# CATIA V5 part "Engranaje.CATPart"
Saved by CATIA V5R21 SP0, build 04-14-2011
Part number: Engranaje
Bounding box of the stored display mesh (mm): x -180 to 0, y -257.469 to 257.464, z -257.469 to 257.468
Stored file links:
  C:\Users\Juan y Virginia\Documents\Cauly\Apuntes\CAD\Catia\Cursos\Engranaje\Engranaje.CATPart
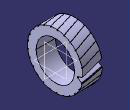
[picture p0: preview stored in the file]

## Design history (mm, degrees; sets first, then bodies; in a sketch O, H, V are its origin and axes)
Parameters
  `Modulo (m)` = 18 mm
  `Numero dientes (z)` = 25
  `Angulo de presion (alfa)` = 25 deg
  `Angulo de helice (beta)` = 15 deg
  `Tipo helice` = 1
  `Diametro eje (dj)` = 100 mm
  `Diametro primitivo (d)` = 465.8743 mm {= `Modulo (m)` *`Numero dientes (z)` /cos(`Angulo de helice (beta)` )}
  `Diametro base (db)` = 422.2255 mm {= `Diametro primitivo (d)` *cos(`Angulo de presion (alfa)` )}
  `Diametro exterior (de)` = 501.8743 mm {= `Diametro primitivo (d)` +2*`Modulo (m)`}
  `Diametro de fondo (df)` = 420.8743 mm {= `Diametro primitivo (d)` -2*`Dedendum (b)`}
  `Paso nominal (pn)` = 56.5487 mm {= PI * `Modulo (m)`}
  `Paso aparente (pa)` = 58.5435 mm {= `Paso nominal (pn)` / cos(`Angulo de helice (beta)` )}
  `Addendum (a)` = 18 mm {= `Modulo (m)`}
  `Dedendum (b)` = 22.5 mm {= 1.25 * `Modulo (m)`}
  `Espacio libre de fondo (c)` = 4.5 mm {= 0.25 * `Modulo (m)`}
  `Profundidad diente (h)` = 40.5 mm {= `Addendum (a)` +`Dedendum (b)`}
  `Radio de pie (r)` = 2.988 mm {= .166 * `Modulo (m)`}
  `Ancho de diente (B)` = 180 mm
  `Diametro de cubo (dc)` = 0 mm
  `Diametro auxiliar (da)` = 356.0743 mm {= `Diametro de fondo (df)` -3.6 * `Modulo (m)`}
  theta1 = 5.9317 deg {= `Ancho de diente (B)` * tan (`Angulo de helice (beta)`) /`Diametro primitivo (d)` *180/PI*1deg}
  theta2 = -5.9317 deg {= -`Ancho de diente (B)` * tan (`Angulo de helice (beta)`) /`Diametro primitivo (d)` *180/PI*1deg}
Set1
  Circle1: type CtrRad, Start 0, End 180, Center {point type Coord, X 0, Y 0, Z 0}, Support yz-plane, Radius 501.8743 {= `Diametro exterior (de)`}, FirstDirection (0, 1, 0)
  Circle2: type CtrRad, Start 0, End 180, Center {point type Coord, X 0, Y 0, Z 0}, Support yz-plane, Radius 465.8743 {= `Diametro primitivo (d)`}, FirstDirection (0, 1, 0)
  Circle3: type CtrRad, Start 0, End 180, Center {point type Coord, X 0, Y 0, Z 0}, Support yz-plane, Radius 422.2255 {= `Diametro base (db)`}, FirstDirection (0, 1, 0)
  Circle4: type CtrRad, Start 0, End 180, Center {point type Coord, X 0, Y 0, Z 0}, Support yz-plane, Radius 420.8743 {= `Diametro de fondo (df)`}, FirstDirection (0, 1, 0)
  Circle5: type CtrRad, Start 0, End 180, Center {point type Coord, X 0, Y 0, Z 0}, Support yz-plane, Radius 356.0743 {= `Diametro auxiliar (da)`}, FirstDirection (0, 1, 0)
  Point1: (0, 211.1127, 0)
  Point2: (0, 214.3037, 0.373)
  Point3: (0, 218.224, 1.2541)
  Point4: (0, 223.5853, 2.9567)
  Point5: (0, 230.2627, 5.7353)
  Point6: (0, 238.0982, 9.8273)
  Point7: (0, 246.9027, 15.4503)
  Point8: (0, 256.4587, 22.7976)
  Plane1: type Offset, RefPlane yz-plane, Offset 90 {= 0.5 * `Ancho de diente (B)`}, reversed
  Plane2: type Offset, RefPlane yz-plane, Offset 180 {= `Ancho de diente (B)`}, reversed
  Point9: (0, 193.1127 {= 0.5 * `Diametro base (db)` -`Modulo (m)`}, 0)
  Line1: type PtDir, LineFirstUpto Plane2, RefPoint {point type Coord, X 0, Y 0, Z 0}, Direction (1, 0, 0), Start 0, End 0
  Rotate1: ToTransfor Sketch2, Axis Line1, Angle 5.9317 {= theta1}
  Rotate2: ToTransfor Sketch1, Axis Line1, Angle -5.9317 {= theta2}
Body1 (main body)
  Pad1: profile Circle1, length 180 {= `Ancho de diente (B)`}
  Pocket1: profile Circle5, length 180 {= `Ancho de diente (B)`}
  Sketch1 on yz-plane, origin (0, 0, 0), H (0, 1, 0), V (0, 0, 1)
  Sketch2 on Plane2, origin (-180, 0, 0), H (0, 1, 0), V (0, 0, 1)
  Sketch3 on Plane1, origin (-90, 0, 0), H (0, 1, 0), V (0, 0, 1)
    projected point E1 (211.1127, 0) from Point1
    projected point E2 (214.3037, 0.373) from Point2
    projected point E3 (218.224, 1.2541) from Point3
    projected point E4 (223.5853, 2.9567) from Point4
    projected point E5 (230.2627, 5.7353) from Point5
    projected point E6 (238.0982, 9.8273) from Point6
    projected point E7 (246.9027, 15.4503) from Point7
    projected point E8 (256.4587, 22.7976) from Point8
    spline S1 through (193.1127, 0) (211.1127, 0) (214.3037, 0.373) (218.224, 1.2541) (223.5853, 2.9567) (230.2627, 5.7353) (238.0982, 9.8273) (246.9027, 15.4503) (256.4587, 22.7976)
    construction arc A1 centre (0, 0) radius 232.9371 from (232.8115, -7.6482) to (232.8324, 6.9853) ccw
    point P1 (232.8324, 6.9853)
    construction line L1 (0, 0) -> (232.8324, 6.9853)
    construction line L2 (0, 0) -> (232.8115, -7.6482)
    projected point E9 (193.1127, 0) from Point9
    spline S2 through (192.6964, -12.6744) (210.6576, -13.8557) (213.8172, -14.4373) (217.6712, -15.5738) (222.9092, -17.6247) (229.3899, -20.8355) (236.9398, -25.433) (245.3563, -31.6216) (254.4095, -39.5803)
    arc A2 centre (0, 0) radius 210.4371 from (210.088, -12.1177) to (210.4303, -1.6969) ccw
    point P3 (210.4371, -0.0447)
    point P4 (209.9864, -13.7667)
    arc A3 centre (212.2302, -1.7114) radius 1.8 from (212.0565, 0.0802) to (210.4303, -1.6969) ccw
    arc A4 centre (0, 0) radius 257.47 from (254.4095, -39.5803) to (256.4587, 22.7976) ccw
    point P8 (254.4095, -39.5803)
    arc A5 centre (211.885, -12.2213) radius 1.8 from (211.594, -13.9977) to (210.088, -12.1177) cw
    point P12 (211.1127, 0)
    point P13 (214.3037, 0.373)
    point P14 (218.224, 1.2541)
    point P15 (223.5853, 2.9567)
    point P16 (230.2627, 5.7353)
    point P17 (238.0982, 9.8273)
    point P18 (246.9027, 15.4503)
    point P19 (256.4587, 22.7976)
    point P20 (193.1127, 0)
    point P21 (254.4095, -39.5803)
    point P22 (192.6964, -12.6744)
    point P23 (245.3563, -31.6216)
    point P24 (236.9398, -25.433)
    point P25 (229.3899, -20.8355)
    point P26 (222.9092, -17.6247)
    point P27 (217.6712, -15.5738)
    point P28 (213.8172, -14.4373)
    point P29 (210.6576, -13.8557)
    radius A1 = 232.9371 {= 0.5 * `Diametro primitivo (d)`}
    angle L1 L2 = 3.6 {= 0.5 * `Paso aparente (pa)` / `Diametro primitivo (d)` *1deg*180/PI}
    radius A2 = 210.4371 {= 0.5 * `Diametro de fondo (df)`}
    radius A3 = 1.8
    radius A5 = 1.8
    coincidence: P12 E1, P13 E2, P14 E3, P15 E4, P16 E5, P17 E6, P18 E7, P19 E8, P1 S1, P20 E9, P3 S1, P4 S2, A2 P3, P21 P8, A2 P4
    symmetry: S1 S2 L2, P19 P21 L2, P20 P22 L2, P18 P23 L2, P17 P24 L2, P16 P25 L2, P15 P26 L2, P14 P27 L2, P13 P28 L2, P12 P29 L2
    tangency: A3 S1, A3 A2, A5 S2, A5 A2
  Loft1: solid, Sections (Rotate2; Sketch3; Rotate1), Spine Line1
  CircPattern1: of Loft1, instances 25 {= `Numero dientes (z)`}, angular step 14.4 {= 2*`Paso aparente (pa)` /`Diametro primitivo (d)` *180/PI* 1deg}, axis from Line1
Relations
  rule "Espesor":
    `Ancho de diente (B)` = 10 * `Modulo (m)`
    if (`Tipo helice` ==3)
    {`Ancho de diente (B)` = 13* `Modulo (m)` }
    /*Rule created by jdelucchi 12/03/2014*/
  theta1 = `Ancho de diente (B)` * tan (`Angulo de helice (beta)`) /`Diametro primitivo (d)` *180/PI*1deg (deactivated)
  rule "Direccion helice" (deactivated):
    /*Rule created by jdelucchi 12/03/2014*/
    theta1 = 0 deg
    theta2 = 0 deg
    if ((((`Tipo helice`  ==1)and`Angulo de helice (beta)` <>0deg))
    	or((`Tipo helice`  ==3)and(`Angulo de helice (beta)` <>0deg)))
    {
    	theta1 = `Ancho de diente (B)` *tan(`Angulo de helice (beta)` )/`Diametro primitivo (d)`
    	*180/PI*1deg
    	theta2 = -`Ancho de diente (B)` *tan(`Angulo de helice (beta)` )/`Diametro primitivo (d)`
    *180/PI*1deg}
    if ((`Tipo helice`  ==2)and(`Angulo de helice (beta)` <>0deg))
    {
    	theta2 =`Ancho de diente (B)` *tan(`Angulo de helice (beta)` )/`Diametro primitivo (d)`
    	*180/PI*1deg
    	theta1 = -`Ancho de diente (B)` *tan(`Angulo de helice (beta)` )/`Diametro primitivo (d)`
    *180/PI*1deg}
